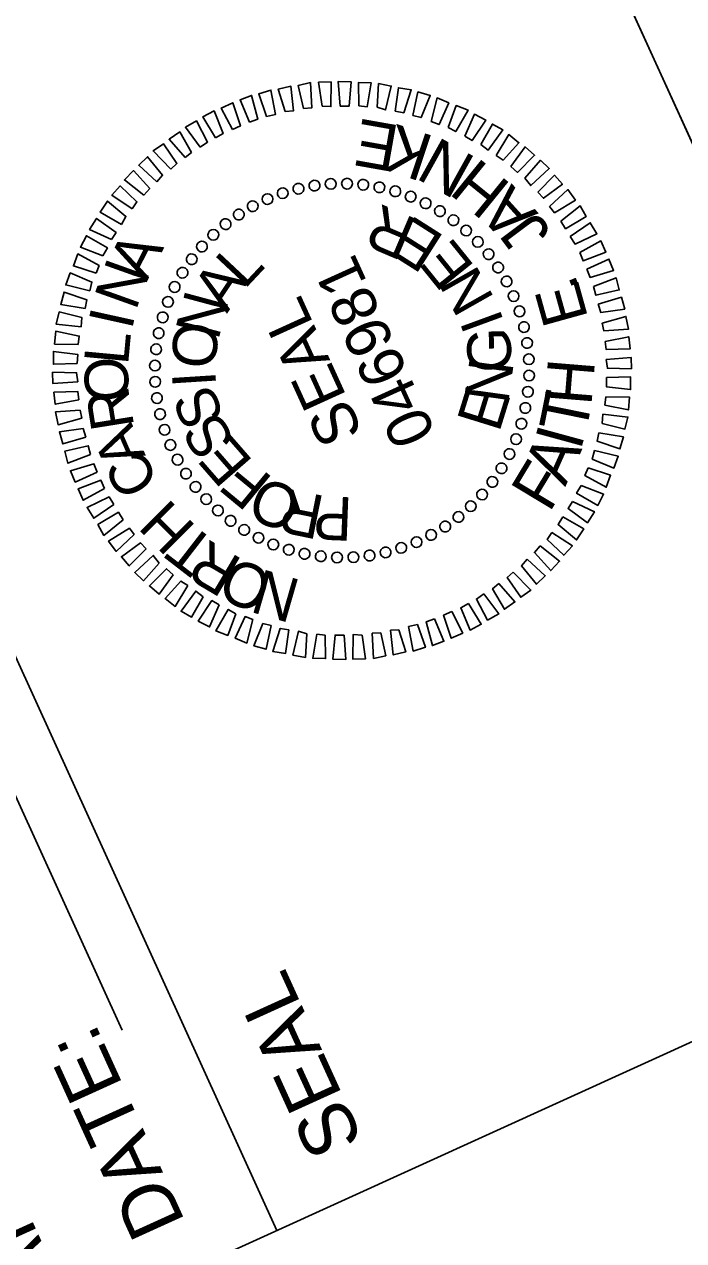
# Model space of a CAD drawing. Extents: x 2097307 to 2099001, y 683921 to 685907.
# Drawn here: x 2097458.2 to 2097546.6, y 685287.8 to 685450.9 of the extents above; entities that cross this region are included whole.
import ezdxf

# ---------------------------------------------------------------- set-up
doc = ezdxf.new("R2010")
doc.units = 0
for name, color, linetype in [('Default', 7, 'Continuous'), ('Sheet Block Title CELL', 7, 'Continuous'), ('Sheet Data Field CELL', 7, 'Continuous'), ('Sheet Layout Plan Border', 7, 'Continuous'), ('Sheet Title CELL', 7, 'Continuous')]:
    doc.layers.add(name, color=color, linetype=linetype)

msp = doc.modelspace()

# ---------------------------------------------------------------- linework, layer by layer
at = {"layer": 'Default'}
for p, q in [((2097499.3, 685429.54), (2097499.3, 685429.54)), ((2097501.49, 685429.54), (2097501.49, 685429.54)), ((2097503.68, 685429.44), (2097503.68, 685429.44)), ((2097492.9, 685428.27), (2097492.9, 685428.27)), ((2097495, 685428.84), (2097495, 685428.84)), ((2097497.1, 685429.3), (2097497.1, 685429.3)), ((2097505.84, 685429.05), (2097505.84, 685429.05)), ((2097507.99, 685428.55), (2097507.99, 685428.55)), ((2097510.02, 685427.82), (2097510.02, 685427.82)), ((2097488.85, 685426.54), (2097488.85, 685426.54)), ((2097490.83, 685427.5), (2097490.83, 685427.5)), ((2097512.07, 685426.94), (2097512.07, 685426.94)), ((2097487.02, 685425.38), (2097487.02, 685425.38)), ((2097513.93, 685425.87), (2097513.93, 685425.87)), ((2097515.77, 685424.61), (2097515.77, 685424.61)), ((2097485.18, 685424.1), (2097485.18, 685424.1)), ((2097517.48, 685423.25), (2097517.48, 685423.25)), ((2097483.52, 685422.68), (2097483.52, 685422.68)), ((2097519.04, 685421.76), (2097519.04, 685421.76)), ((2097482.03, 685421.13), (2097482.03, 685421.13)), ((2097520.46, 685420.1), (2097520.46, 685420.1)), ((2097480.67, 685419.41), (2097480.67, 685419.41)), ((2097521.73, 685418.26), (2097521.73, 685418.26)), ((2097479.42, 685417.58), (2097479.42, 685417.58)), ((2097522.89, 685416.43), (2097522.89, 685416.43)), ((2097478.34, 685415.71), (2097478.34, 685415.71)), ((2097477.46, 685413.67), (2097477.46, 685413.67)), ((2097523.85, 685414.45), (2097523.85, 685414.45)), ((2097476.74, 685411.63), (2097476.74, 685411.63)), ((2097524.63, 685412.39), (2097524.63, 685412.39)), ((2097525.2, 685410.28), (2097525.2, 685410.28)), ((2097476.23, 685409.48), (2097476.23, 685409.48)), ((2097475.84, 685407.33), (2097475.84, 685407.33)), ((2097525.66, 685408.19), (2097525.66, 685408.19)), ((2097475.74, 685405.14), (2097475.74, 685405.14)), ((2097525.89, 685405.98), (2097525.89, 685405.98)), ((2097500.82, 685404.46), (2097500.82, 685404.46)), ((2097525.9, 685403.79), (2097525.9, 685403.79)), ((2097475.75, 685402.94), (2097475.75, 685402.94)), ((2097475.98, 685400.74), (2097475.98, 685400.74)), ((2097525.8, 685401.6), (2097525.8, 685401.6)), ((2097476.44, 685398.64), (2097476.44, 685398.64)), ((2097525.4, 685399.45), (2097525.4, 685399.45)), ((2097524.9, 685397.29), (2097524.9, 685397.29)), ((2097477.01, 685396.54), (2097477.01, 685396.54)), ((2097524.18, 685395.26), (2097524.18, 685395.26)), ((2097477.79, 685394.48), (2097477.79, 685394.48)), ((2097478.74, 685392.5), (2097478.74, 685392.5)), ((2097523.3, 685393.21), (2097523.3, 685393.21)), ((2097479.91, 685390.66), (2097479.91, 685390.66)), ((2097522.22, 685391.35), (2097522.22, 685391.35)), ((2097481.18, 685388.83), (2097481.18, 685388.83)), ((2097520.97, 685389.52), (2097520.97, 685389.52)), ((2097482.6, 685387.16), (2097482.6, 685387.16)), ((2097519.61, 685387.8), (2097519.61, 685387.8)), ((2097484.15, 685385.67), (2097484.15, 685385.67)), ((2097518.12, 685386.24), (2097518.12, 685386.24)), ((2097485.87, 685384.31), (2097485.87, 685384.31)), ((2097516.46, 685384.83), (2097516.46, 685384.83)), ((2097487.71, 685383.06), (2097487.71, 685383.06)), ((2097512.79, 685382.39), (2097512.79, 685382.39)), ((2097514.62, 685383.55), (2097514.62, 685383.55)), ((2097489.57, 685381.99), (2097489.57, 685381.99)), ((2097491.62, 685381.11), (2097491.62, 685381.11)), ((2097508.74, 685380.66), (2097508.74, 685380.66)), ((2097510.81, 685381.43), (2097510.81, 685381.43)), ((2097493.65, 685380.38), (2097493.65, 685380.38)), ((2097495.8, 685379.88), (2097495.8, 685379.88)), ((2097497.96, 685379.49), (2097497.96, 685379.49)), ((2097500.15, 685379.38), (2097500.15, 685379.38)), ((2097502.34, 685379.39), (2097502.34, 685379.39)), ((2097504.54, 685379.62), (2097504.54, 685379.62)), ((2097506.64, 685380.08), (2097506.64, 685380.08))]:
    msp.add_line(p, q, dxfattribs=at)
for points in [[(2097493.19, 685439.22), (2097492.27, 685442.21), (2097493.96, 685442.6), (2097494.31, 685439.3)], [(2097495.64, 685439.63), (2097494.95, 685442.72), (2097496.59, 685443.08), (2097496.76, 685439.7)], [(2097498.14, 685439.94), (2097497.67, 685443.13), (2097499.35, 685443.18), (2097499.32, 685439.87)], [(2097500.55, 685439.94), (2097500.31, 685443.24), (2097502.04, 685443.2), (2097501.76, 685439.94)], [(2097503.06, 685439.98), (2097503.02, 685443.09), (2097504.74, 685443.05), (2097504.17, 685439.83)], [(2097505.51, 685439.78), (2097505.72, 685442.95), (2097507.41, 685442.62), (2097506.66, 685439.42)], [(2097488.41, 685437.77), (2097487.16, 685440.77), (2097488.7, 685441.36), (2097489.55, 685438.17)], [(2097490.7, 685438.53), (2097489.65, 685441.57), (2097491.28, 685442.09), (2097491.9, 685438.8)], [(2097507.96, 685439.24), (2097508.38, 685442.4), (2097510.1, 685442.14), (2097509.09, 685439.04)], [(2097510.31, 685438.66), (2097511, 685441.84), (2097512.64, 685441.38), (2097511.41, 685438.4)], [(2097512.76, 685437.86), (2097513.57, 685441.03), (2097515.13, 685440.37), (2097513.82, 685437.46)], [(2097483.86, 685435.69), (2097482.15, 685438.49), (2097483.66, 685439.28), (2097484.91, 685436.28)], [(2097486.12, 685436.78), (2097484.63, 685439.67), (2097486.18, 685440.38), (2097487.21, 685437.27)], [(2097515.04, 685437.08), (2097516.13, 685440), (2097517.72, 685439.4), (2097516.07, 685436.51)], [(2097481.8, 685434.43), (2097479.82, 685437.1), (2097481.3, 685437.94), (2097482.81, 685435.11)], [(2097517.28, 685435.9), (2097518.57, 685438.85), (2097520.08, 685438.06), (2097518.26, 685435.31)], [(2097479.8, 685433.02), (2097477.63, 685435.5), (2097479.06, 685436.48), (2097480.63, 685433.73)], [(2097519.43, 685434.79), (2097520.98, 685437.53), (2097522.39, 685436.75), (2097520.43, 685434.04)], [(2097521.48, 685433.31), (2097523.17, 685436.11), (2097524.54, 685435.03), (2097522.42, 685432.69)], [(2097477.87, 685431.48), (2097475.49, 685433.92), (2097476.87, 685434.88), (2097478.68, 685432.24)], [(2097523.46, 685431.85), (2097525.35, 685434.47), (2097526.62, 685433.35), (2097524.32, 685431.04)], [(2097476.01, 685429.76), (2097473.57, 685432), (2097474.75, 685433.14), (2097476.76, 685430.65)], [(2097474.25, 685427.97), (2097471.66, 685430.03), (2097472.85, 685431.29), (2097475.04, 685428.88)], [(2097525.33, 685430.28), (2097527.43, 685432.67), (2097528.59, 685431.55), (2097526.12, 685429.27)], [(2097527.07, 685428.38), (2097529.32, 685430.67), (2097530.37, 685429.45), (2097527.82, 685427.57)], [(2097472.7, 685426.17), (2097469.95, 685427.99), (2097471.09, 685429.23), (2097473.32, 685427.11)], [(2097528.65, 685426.47), (2097531.09, 685428.73), (2097532.11, 685427.33), (2097529.32, 685425.62)], [(2097471.24, 685424.07), (2097468.41, 685425.7), (2097469.39, 685427.19), (2097471.86, 685425.13)], [(2097530.15, 685424.51), (2097532.73, 685426.57), (2097533.55, 685425.13), (2097530.78, 685423.48)], [(2097469.91, 685422.04), (2097466.99, 685423.4), (2097467.91, 685424.87), (2097470.53, 685422.98)], [(2097531.42, 685422.45), (2097534.1, 685424.28), (2097534.99, 685422.81), (2097532.05, 685421.42)], [(2097468.76, 685419.87), (2097465.76, 685421.03), (2097466.55, 685422.55), (2097469.38, 685420.92)], [(2097532.68, 685420.28), (2097535.53, 685421.85), (2097536.17, 685420.33), (2097533.13, 685419.17)], [(2097467.85, 685417.53), (2097464.82, 685418.51), (2097465.41, 685420.1), (2097468.26, 685418.54)], [(2097533.63, 685418.07), (2097536.59, 685419.42), (2097537.22, 685417.9), (2097534.08, 685416.96)], [(2097467, 685415.17), (2097463.78, 685415.96), (2097464.38, 685417.55), (2097467.29, 685416.34)], [(2097534.53, 685415.74), (2097537.57, 685416.9), (2097537.98, 685415.28), (2097534.84, 685414.56)], [(2097466.37, 685412.8), (2097463.11, 685413.34), (2097463.57, 685414.98), (2097466.62, 685413.95)], [(2097535.16, 685413.39), (2097538.26, 685414.3), (2097538.71, 685412.7), (2097535.52, 685412.23)], [(2097465.86, 685410.31), (2097462.49, 685410.7), (2097462.91, 685412.32), (2097465.95, 685411.56)], [(2097535.71, 685410.84), (2097538.88, 685411.73), (2097539.22, 685410.02), (2097535.92, 685409.78)], [(2097465.44, 685407.97), (2097462.28, 685408.02), (2097462.44, 685409.74), (2097465.59, 685409.09)], [(2097536.11, 685408.38), (2097539.25, 685408.99), (2097539.43, 685407.37), (2097536.23, 685407.28)], [(2097465.34, 685405.41), (2097462.14, 685405.32), (2097462.14, 685407.02), (2097465.39, 685406.63)], [(2097536.23, 685405.96), (2097539.57, 685406.22), (2097539.6, 685404.7), (2097536.39, 685404.77)], [(2097465.41, 685402.96), (2097462.07, 685402.71), (2097462.03, 685404.23), (2097465.25, 685404.16)], [(2097536.29, 685403.52), (2097539.5, 685403.61), (2097539.5, 685401.91), (2097536.25, 685402.29)], [(2097465.52, 685400.54), (2097462.39, 685399.94), (2097462.2, 685401.56), (2097465.41, 685401.64)], [(2097536.2, 685400.95), (2097539.35, 685400.9), (2097539.2, 685399.19), (2097536.05, 685399.84)], [(2097465.93, 685398.09), (2097462.76, 685397.2), (2097462.42, 685398.91), (2097465.72, 685399.15)], [(2097535.78, 685398.62), (2097539.14, 685398.23), (2097538.73, 685396.61), (2097535.69, 685397.37)], [(2097466.48, 685395.54), (2097463.38, 685394.62), (2097462.93, 685396.23), (2097466.12, 685396.69)], [(2097535.26, 685396.13), (2097538.53, 685395.59), (2097538.07, 685393.95), (2097535.02, 685394.98)], [(2097467.11, 685393.19), (2097464.07, 685392.03), (2097463.66, 685393.65), (2097466.8, 685394.37)], [(2097534.64, 685393.76), (2097537.85, 685392.97), (2097537.26, 685391.38), (2097534.35, 685392.58)], [(2097468.01, 685390.85), (2097465.05, 685389.51), (2097464.41, 685391.03), (2097467.56, 685391.97)], [(2097533.79, 685391.4), (2097536.82, 685390.41), (2097536.23, 685388.82), (2097533.37, 685390.38)], [(2097468.96, 685388.65), (2097466.1, 685387.07), (2097465.47, 685388.6), (2097468.51, 685389.76)], [(2097532.88, 685389.06), (2097535.88, 685387.9), (2097535.09, 685386.38), (2097532.26, 685388.01)], [(2097470.22, 685386.48), (2097467.54, 685384.65), (2097466.65, 685386.11), (2097469.59, 685387.51)], [(2097471.49, 685384.42), (2097468.91, 685382.36), (2097468.09, 685383.8), (2097470.85, 685385.45)], [(2097531.72, 685386.89), (2097534.65, 685385.53), (2097533.72, 685384.06), (2097531.11, 685385.95)], [(2097530.4, 685384.85), (2097533.22, 685383.23), (2097532.25, 685381.74), (2097529.78, 685383.8)], [(2097472.98, 685382.46), (2097470.55, 685380.2), (2097469.53, 685381.6), (2097472.32, 685383.31)], [(2097528.93, 685382.76), (2097531.69, 685380.94), (2097530.54, 685379.7), (2097528.32, 685381.82)], [(2097474.57, 685380.54), (2097472.31, 685378.25), (2097471.26, 685379.48), (2097473.82, 685381.35)], [(2097527.39, 685380.96), (2097529.98, 685378.89), (2097528.79, 685377.64), (2097526.6, 685380.05)], [(2097476.31, 685378.64), (2097474.21, 685376.26), (2097473.04, 685377.38), (2097475.52, 685379.66)], [(2097525.62, 685379.17), (2097528.07, 685376.93), (2097526.89, 685375.79), (2097524.88, 685378.28)], [(2097478.18, 685377.08), (2097476.29, 685374.46), (2097475.01, 685375.58), (2097477.31, 685377.89)], [(2097523.77, 685377.44), (2097526.14, 685375.01), (2097524.77, 685374.05), (2097522.96, 685376.69)], [(2097480.16, 685375.62), (2097478.47, 685372.82), (2097477.1, 685373.89), (2097479.22, 685376.23)], [(2097521.84, 685375.9), (2097524, 685373.43), (2097522.58, 685372.45), (2097521, 685375.2)], [(2097482.21, 685374.13), (2097480.66, 685371.39), (2097479.25, 685372.18), (2097481.21, 685374.89)], [(2097519.84, 685374.5), (2097521.82, 685371.83), (2097520.34, 685370.99), (2097518.83, 685373.82)], [(2097484.36, 685373.02), (2097483.07, 685370.07), (2097481.55, 685370.87), (2097483.38, 685373.62)], [(2097486.6, 685371.85), (2097485.51, 685368.93), (2097483.92, 685369.53), (2097485.57, 685372.42)], [(2097517.78, 685373.23), (2097519.49, 685370.44), (2097517.98, 685369.65), (2097516.73, 685372.64)], [(2097488.88, 685371.07), (2097488.07, 685367.9), (2097486.5, 685368.56), (2097487.82, 685371.47)], [(2097513.23, 685371.16), (2097514.48, 685368.16), (2097512.94, 685367.57), (2097512.09, 685370.76)], [(2097515.52, 685372.15), (2097517, 685369.26), (2097515.46, 685368.55), (2097514.43, 685371.65)], [(2097491.33, 685370.26), (2097490.63, 685367.09), (2097489, 685367.55), (2097490.22, 685370.53)], [(2097493.68, 685369.68), (2097493.25, 685366.52), (2097491.54, 685366.79), (2097492.55, 685369.88)], [(2097496.12, 685369.15), (2097495.92, 685365.98), (2097494.23, 685366.31), (2097494.97, 685369.5)], [(2097498.58, 685368.95), (2097498.62, 685365.83), (2097496.9, 685365.88), (2097497.46, 685369.1)], [(2097503.5, 685368.99), (2097503.97, 685365.8), (2097502.29, 685365.74), (2097502.32, 685369.06)], [(2097506, 685369.3), (2097506.69, 685366.21), (2097505.04, 685365.85), (2097504.88, 685369.23)], [(2097508.45, 685369.7), (2097509.37, 685366.72), (2097507.68, 685366.33), (2097507.33, 685369.63)], [(2097510.94, 685370.4), (2097511.99, 685367.36), (2097510.36, 685366.84), (2097509.74, 685370.13)], [(2097501.09, 685368.99), (2097501.32, 685365.69), (2097499.6, 685365.73), (2097499.88, 685368.99)]]:
    msp.add_lwpolyline(points, close=True, dxfattribs=at)
for centre, major_axis in [((2097494.98, 685428.85), (-0.168, 0.7)), ((2097497.13, 685429.27), (-0.106, 0.712)), ((2097499.3, 685429.5), (-0.044, 0.719)), ((2097501.49, 685429.53), (0.019, 0.72)), ((2097503.67, 685429.38), (0.082, 0.715)), ((2097505.83, 685429.04), (0.144, 0.705)), ((2097490.83, 685427.47), (-0.287, 0.66)), ((2097492.87, 685428.25), (-0.228, 0.683)), ((2097507.96, 685428.51), (0.205, 0.69)), ((2097510.02, 685427.79), (0.264, 0.67)), ((2097486.99, 685425.39), (-0.397, 0.601)), ((2097488.86, 685426.51), (-0.343, 0.633)), ((2097512.02, 685426.9), (0.322, 0.644)), ((2097513.94, 685425.84), (0.377, 0.614)), ((2097485.22, 685424.1), (-0.448, 0.564)), ((2097515.75, 685424.62), (0.429, 0.579)), ((2097483.57, 685422.67), (-0.495, 0.523)), ((2097517.45, 685423.24), (0.477, 0.539)), ((2097482.04, 685421.09), (-0.539, 0.477)), ((2097519.02, 685421.72), (0.523, 0.495)), ((2097480.67, 685419.39), (-0.579, 0.429)), ((2097520.46, 685420.07), (0.564, 0.448)), ((2097479.44, 685417.58), (-0.614, 0.377)), ((2097521.74, 685418.29), (0.601, 0.397)), ((2097478.38, 685415.67), (-0.644, 0.322)), ((2097522.87, 685416.42), (0.633, 0.343)), ((2097523.82, 685414.45), (0.66, 0.287)), ((2097477.49, 685413.67), (-0.67, 0.264)), ((2097524.61, 685412.41), (0.683, 0.228)), ((2097476.78, 685411.6), (-0.69, 0.205)), ((2097476.25, 685409.48), (-0.705, 0.144)), ((2097525.21, 685410.3), (0.7, 0.168)), ((2097525.63, 685408.16), (0.712, 0.106)), ((2097475.9, 685407.32), (-0.715, 0.082)), ((2097525.85, 685405.98), (0.719, 0.044)), ((2097475.75, 685405.13), (-0.72, 0.019)), ((2097475.78, 685402.95), (-0.719, -0.044)), ((2097525.89, 685403.79), (0.72, -0.019)), ((2097525.74, 685401.61), (0.715, -0.082)), ((2097476.01, 685400.77), (-0.712, -0.106)), ((2097525.39, 685399.45), (0.705, -0.144)), ((2097476.43, 685398.62), (-0.7, -0.168)), ((2097477.03, 685396.52), (-0.683, -0.228)), ((2097524.86, 685397.33), (0.69, -0.205)), ((2097477.81, 685394.48), (-0.66, -0.287)), ((2097524.15, 685395.26), (0.67, -0.264)), ((2097523.26, 685393.26), (0.644, -0.322)), ((2097478.77, 685392.51), (-0.633, -0.343)), ((2097522.2, 685391.35), (0.614, -0.377)), ((2097479.9, 685390.63), (-0.601, -0.397)), ((2097520.97, 685389.53), (0.579, -0.429)), ((2097481.18, 685388.86), (-0.564, -0.448)), ((2097519.59, 685387.83), (0.539, -0.477)), ((2097482.62, 685387.21), (-0.523, -0.495)), ((2097518.07, 685386.26), (0.495, -0.523)), ((2097484.19, 685385.69), (-0.477, -0.539)), ((2097516.42, 685384.83), (0.448, -0.564)), ((2097485.89, 685384.31), (-0.429, -0.579)), ((2097487.7, 685383.09), (-0.377, -0.614)), ((2097514.65, 685383.54), (0.397, -0.601)), ((2097489.62, 685382.03), (-0.322, -0.644)), ((2097510.81, 685381.46), (0.287, -0.66)), ((2097512.77, 685382.42), (0.343, -0.633)), ((2097491.61, 685381.13), (-0.264, -0.67)), ((2097493.68, 685380.42), (-0.205, -0.69)), ((2097495.8, 685379.89), (-0.144, -0.705)), ((2097506.66, 685380.07), (0.168, -0.7)), ((2097508.76, 685380.68), (0.228, -0.683)), ((2097497.97, 685379.55), (-0.082, -0.715)), ((2097500.15, 685379.39), (-0.019, -0.72)), ((2097502.34, 685379.43), (0.044, -0.719)), ((2097504.51, 685379.66), (0.106, -0.712))]:
    msp.add_ellipse(centre, major_axis=major_axis, ratio=0.999708, dxfattribs=at)
at = {"layer": 'Sheet Block Title CELL'}
msp.add_lwpolyline([(2097593.2, 685335.14), (2097510.34, 685517.23), (2097534.24, 685528.11), (2097617.1, 685346.01)], close=True, dxfattribs=at)
at = {"layer": 'Sheet Layout Plan Border'}
msp.add_lwpolyline([(2098458.66, 685511.51), (2098911.14, 684517.12), (2097955.44, 684082.23), (2097420.98, 685256.77), (2097639.51, 685356.21), (2097584.97, 685476.06), (2098243.4, 685773.28), (2098379.01, 685475.27)], close=True, dxfattribs=at)
at = {"layer": 'Sheet Title CELL'}
for p, q in [((2097506.4, 685525.9), (2097593.2, 685335.14)), ((2097492.07, 685289.12), (2097405.27, 685479.88)), ((2097471.33, 685315.99), (2097402.19, 685467.93)), ((2097420.98, 685256.77), (2097593.2, 685335.14))]:
    msp.add_line(p, q, dxfattribs=at)

# ---------------------------------------------------------------- texts
at = {"layer": 'Default'}
for s, height, rotation, p in [('E', 6.29, 169.9604, (2097508.73, 685437.29)), ('K', 6.36, 161.6765, (2097513.37, 685435.81)), ('N', 6.36, 150.9507, (2097518.99, 685432.92)), ('H', 6.27, 140.9667, (2097523.65, 685429.34)), ('A', 6.15, 132.1264, (2097527.2, 685425.54)), ('R', 5.99, 156.9488, (2097511.13, 685424.65)), ('E', 5.96, 147.5915, (2097514.74, 685422.39)), ('J', 6.08, 126.8686, (2097529.02, 685423.03)), ('A', 5.95, 63.0846, (2097474.62, 685416.28)), ('E', 5.74, 128.8792, (2097518.71, 685418.37)), ('L', 5.79, 46.8683, (2097487.72, 685415.26)), ('046981', 5.998, 114.4674, (2097513.48, 685395.97)), ('N', 5.99, 70.2863, (2097473.16, 685412.37)), ('N', 5.65, 119.5238, (2097521.31, 685414.12)), ('A', 5.89, 56.2277, (2097485.39, 685412.05)), ('E', 6.04, 105.5251, (2097533.84, 685411.5)), ('.', 6, 112.6344, (2097532.72, 685415.53)), ('N', 5.99, 74.944, (2097484.2, 685408.38)), ('SEAL', 5.998, 114.4674, (2097503.69, 685396.1)), ('I', 5.98, 77.4876, (2097472.64, 685409.77)), ('I', 5.65, 110.1686, (2097522.56, 685411.01)), ('O', 5.94, 84.3009, (2097483.77, 685404.51)), ('L', 5.93, 84.6883, (2097472.13, 685405.09)), ('G', 5.86, 91.4577, (2097523.55, 685404.26)), ('O', 5.85, 91.8886, (2097472.27, 685400.32)), ('N', 5.95, 82.1014, (2097523.07, 685399.87)), ('H', 6.3, 85.3408, (2097534.24, 685399.67)), ('I', 5.83, 93.657, (2097483.96, 685402.4)), ('R', 5.75, 99.0885, (2097472.98, 685396.96)), ('S', 5.64, 112.3678, (2097485.11, 685398.19)), ('E', 5.99, 72.7443, (2097521.86, 685396.02)), ('T', 6.36, 78.5405, (2097533.44, 685395.75)), ('S', 5.67, 121.723, (2097486.64, 685394.94)), ('A', 5.64, 113.4877, (2097474.53, 685393.05)), ('I', 6.37, 74.7386, (2097532.79, 685393.6)), ('E', 5.77, 131.0785, (2097489.03, 685392.23)), ('A', 6.35, 65.8983, (2097530.74, 685388.82)), ('C', 5.66, 120.6873, (2097476.44, 685389.58)), ('F', 6.29, 58.8817, (2097528.6, 685385.28)), ('F', 5.89, 140.4344, (2097491.72, 685389.94)), ('O', 5.98, 159.1487, (2097495.77, 685388.16)), ('R', 5.93, 168.5071, (2097498.72, 685387.58)), ('H', 5.82, 135.0869, (2097481.41, 685383.49)), ('P', 5.84, 177.8663, (2097502.3, 685387.45)), ('T', 5.91, 142.2872, (2097484.26, 685381.22)), ('R', 5.97, 149.4879, (2097487.67, 685379.03)), ('O', 5.99, 156.6892, (2097491.92, 685377.18)), ('N', 5.96, 163.8909, (2097495.51, 685376.29))]:
    msp.add_text(s, height=height, rotation=rotation, dxfattribs=at).set_placement(p)
at = {"layer": 'Sheet Data Field CELL'}
for s, p in [('APPROVED:', (2097462.89, 685282.53)), ('SEAL', (2097503.72, 685301.11)), ('DATE:', (2097479.86, 685290.25))]:
    msp.add_text(s, height=7.512, rotation=114.4674, dxfattribs=at).set_placement(p)

doc.saveas('drawing.dxf')
